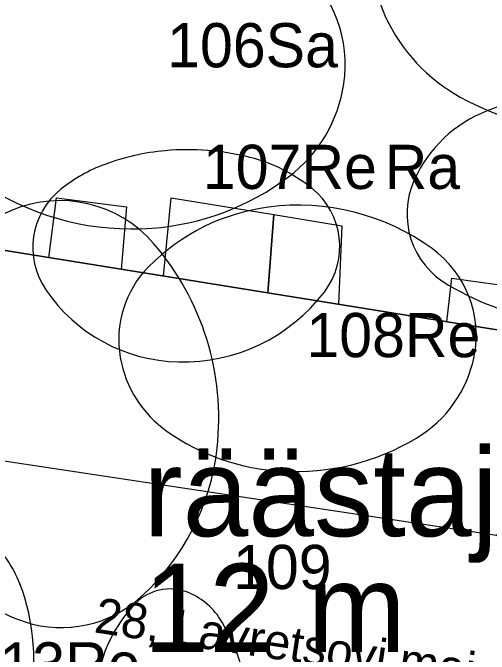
# Model space of a CAD drawing. Extents: x 738423 to 738903, y 6589762 to 6590172.
# Drawn here: x 738736.84 to 738753.01, y 6589853.54 to 6589875.33 of the extents above; entities that cross this region are included whole.
import ezdxf

# ---------------------------------------------------------------- set-up
doc = ezdxf.new("R2010")
doc.units = 0
for name, color, linetype in [('_1927_hoonestus', 7, 'Continuous'), ('_1927_katuse_kalded', 7, 'Continuous'), ('_a_olol_maapind', 7, 'Continuous'), ('_ajalooline_aadress', 7, 'Continuous'), ('a_dendro_II_Vkl_puu', 7, 'Continuous'), ('a_dendro_III_vk_puu', 7, 'Continuous'), ('a_dendro_puu_nr', 7, 'Continuous'), ('a_dendro_V_vk_puu', 7, 'Continuous'), ('Default', 7, 'Continuous')]:
    doc.layers.add(name, color=color, linetype=linetype)

# ---------------------------------------------------------------- blocks, each defined once
blk = doc.blocks.new('_U500')
at = {"layer": 'Default'}
for centre, radius, start, end in [((-0.003181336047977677, 0.010726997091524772), 0.005594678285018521, 70.00824536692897, 154.4975713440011), ((-0.004341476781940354, 0.007538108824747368), 0.008988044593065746, 25.436486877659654, 70.00824536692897), ((0.011580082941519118, 0.0036853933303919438), 0.021949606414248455, 154.49757134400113, 194.18050981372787), ((-0.018263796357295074, 0.0009164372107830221), 0.024404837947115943, 358.8256663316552, 25.436486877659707), ((-0.0137456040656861, 0.0008238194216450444), 0.019885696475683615, 335.045242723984, 358.8256663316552), ((0.0065598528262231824, 0.0024168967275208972), 0.01677159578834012, 194.18050981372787, 228.62130685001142), ((-0.0020266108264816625, -0.004629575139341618), 0.006959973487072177, 294.2825804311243, 335.045242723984), ((-0.0012209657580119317, -0.006415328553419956), 0.005000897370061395, 228.6213068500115, 294.2825804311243)]:
    blk.add_arc(centre, radius, start, end, dxfattribs=at)
blk = doc.blocks.new('_U502')
at = {"layer": 'Default'}
for centre, radius, start, end in [((0.0036572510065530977, 0.004633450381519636), 0.00959048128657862, 55.41358266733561, 119.34866517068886), ((0.004842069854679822, 0.0025263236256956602), 0.012007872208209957, 119.34866517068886, 155.37187783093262), ((-0.0003045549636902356, -0.0011124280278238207), 0.016569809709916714, 7.908336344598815, 55.413582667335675), ((0.010745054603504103, -0.00017977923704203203), 0.018501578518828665, 155.37187783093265, 184.22093899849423), ((-0.0007628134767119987, -0.0011760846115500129), 0.017032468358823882, 317.51230780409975, 7.908336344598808), ((0.010991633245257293, -0.00016158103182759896), 0.018748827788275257, 184.2209389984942, 213.03615061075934), ((0.005634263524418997, -0.0036455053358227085), 0.01235827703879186, 213.03615061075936, 248.72963133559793), ((0.004661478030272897, -0.006144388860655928), 0.009676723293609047, 248.72963133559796, 317.51230780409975)]:
    blk.add_arc(centre, radius, start, end, dxfattribs=at)
blk = doc.blocks.new('_U555')
at = {"layer": 'Default'}
for centre, radius, start, end in [((-0.004312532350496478, 0.003536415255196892), 0.0050895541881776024, 43.03836195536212, 128.56530609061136), ((-0.0004914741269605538, -0.0012560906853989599), 0.011218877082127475, 128.5653060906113, 182.99361229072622), ((-0.0083944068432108, -0.0002751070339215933), 0.010674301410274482, 24.572702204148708, 43.03836195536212), ((-0.013301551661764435, -0.0025189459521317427), 0.01607012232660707, 9.545113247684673, 24.57270220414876), ((-0.014308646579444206, -0.002688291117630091), 0.01709135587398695, 349.9959315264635, 9.545113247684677), ((0.0004151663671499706, -0.0012086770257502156), 0.012126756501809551, 182.99361229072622, 236.8517005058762), ((-0.008353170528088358, -0.003738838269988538), 0.011043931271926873, 325.61057428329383, 349.99593152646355), ((-0.0034354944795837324, -0.007104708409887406), 0.005084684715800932, 236.85170050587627, 325.61057428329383)]:
    blk.add_arc(centre, radius, start, end, dxfattribs=at)
blk = doc.blocks.new('_U556')
at = {"layer": 'Default'}
for centre, radius, start, end in [((0.0008585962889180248, 0.005017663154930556), 0.009782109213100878, 101.92949833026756, 152.32783538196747), ((0.0007009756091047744, 0.005763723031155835), 0.009019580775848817, 44.06830731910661, 101.92949833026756), ((-0.005511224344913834, -0.0002496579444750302), 0.017665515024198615, 3.6239622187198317, 44.06830731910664), ((0.008453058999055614, 0.0010351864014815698), 0.018357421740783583, 152.32783538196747, 188.54277977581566), ((-0.004957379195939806, -0.0002145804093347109), 0.017110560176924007, 323.29399507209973, 3.623962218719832), ((0.007725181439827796, 0.0009258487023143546), 0.017621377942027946, 188.54277977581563, 221.24473871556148), ((0.0016930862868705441, -0.005172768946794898), 0.00881524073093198, 265.8876585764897, 323.29399507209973), ((0.0017552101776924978, -0.0043087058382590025), 0.009681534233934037, 221.24473871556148, 265.8876585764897)]:
    blk.add_arc(centre, radius, start, end, dxfattribs=at)
blk = doc.blocks.new('_U557')
at = {"layer": 'Default'}
for centre, radius, start, end in [((0.0009168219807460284, 0.0031891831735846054), 0.007029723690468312, 49.6852980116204, 104.286675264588), ((0.001109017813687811, 0.0024344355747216), 0.007808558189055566, 104.286675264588, 149.17299111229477), ((-0.0036199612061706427, -0.0021576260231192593), 0.014041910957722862, 11.811793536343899, 49.68529801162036), ((0.0072482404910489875, -0.0012291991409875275), 0.014957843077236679, 149.17299111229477, 181.19652175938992), ((-0.005001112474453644, -0.0024464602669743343), 0.015452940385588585, 328.31163125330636, 11.811793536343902), ((0.008365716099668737, -0.0012058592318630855), 0.016075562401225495, 181.1965217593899, 215.2100419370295), ((0.0020888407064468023, -0.005635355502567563), 0.008393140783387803, 215.21004193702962, 262.96527315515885), ((0.0019526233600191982, -0.006739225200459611), 0.007280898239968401, 262.96527315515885, 328.31163125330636)]:
    blk.add_arc(centre, radius, start, end, dxfattribs=at)
blk = doc.blocks.new('_U560')
at = {"layer": 'Default'}
for centre, radius, start, end in [((0.00339859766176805, -0.012089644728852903), 0.019710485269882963, 70.12675947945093, 101.72724357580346), ((0.0030405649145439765, -0.010364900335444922), 0.01794897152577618, 101.72724357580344, 129.22704303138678), ((0.006378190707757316, -0.0038465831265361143), 0.01094543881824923, 27.263791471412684, 70.12675947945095), ((-0.00200913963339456, -0.004179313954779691), 0.009963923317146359, 129.22704303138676, 166.43322505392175), ((0.008627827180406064, -0.00268725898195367), 0.008414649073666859, 315.1631984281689, 27.263791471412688), ((-0.00387483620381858, -0.00372909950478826), 0.008044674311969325, 166.43322505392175, 226.4566374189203), ((0.001714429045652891, 0.004186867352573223), 0.01816394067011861, 267.93816240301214, 315.1631984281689), ((0.0016382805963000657, 0.0020717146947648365), 0.01604741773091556, 226.45663741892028, 267.93816240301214)]:
    blk.add_arc(centre, radius, start, end, dxfattribs=at)
blk = doc.blocks.new('_U561')
at = {"layer": 'Default'}
for centre, radius, start, end in [((-0.0032471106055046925, -0.010129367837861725), 0.014437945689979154, 78.49437099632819, 117.35483362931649), ((-0.0019616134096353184, -0.0038141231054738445), 0.007993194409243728, 50.23157484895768, 78.49437099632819), ((-0.008165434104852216, -0.0006226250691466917), 0.0037342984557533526, 117.35483362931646, 199.0584050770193), ((0.0013930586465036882, 0.00021679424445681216), 0.0027489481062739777, 1.026623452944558, 50.23157484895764), ((0.0011186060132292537, 0.00021187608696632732), 0.003023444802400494, 318.0268318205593, 1.0266234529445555), ((-0.007242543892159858, -0.00030379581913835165), 0.004710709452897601, 199.0584050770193, 259.8390365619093), ((-0.003091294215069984, 0.0039989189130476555), 0.008686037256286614, 293.05157128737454, 318.0268318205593), ((-0.0054696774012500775, 0.009588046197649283), 0.014760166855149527, 259.8390365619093, 293.0515712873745)]:
    blk.add_arc(centre, radius, start, end, dxfattribs=at)
blk = doc.blocks.new('_U563')
at = {"layer": 'Default'}
for centre, radius, start, end in [((-0.0011498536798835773, -0.006309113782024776), 0.012338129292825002, 87.06210191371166, 129.99611641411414), ((-0.001004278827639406, -0.003472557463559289), 0.009497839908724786, 49.93101198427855, 87.06210191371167), ((0.0030244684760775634, 0.0013169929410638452), 0.003239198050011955, 343.8549831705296, 49.93101198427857), ((-0.006769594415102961, 0.0003891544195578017), 0.003594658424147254, 129.99611641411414, 215.3727263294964), ((0.001656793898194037, 0.0017129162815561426), 0.004663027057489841, 307.1223988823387, 343.8549831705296), ((-0.004839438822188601, 0.001759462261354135), 0.005961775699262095, 215.3727263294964, 257.0506083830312), ((-0.0024608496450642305, 0.007152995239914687), 0.011485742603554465, 283.95889134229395, 307.1223988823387), ((-0.003052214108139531, 0.009532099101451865), 0.013937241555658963, 257.05060838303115, 283.95889134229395)]:
    blk.add_arc(centre, radius, start, end, dxfattribs=at)

msp = doc.modelspace()

# ---------------------------------------------------------------- linework, layer by layer
at = {"layer": '_1927_hoonestus'}
for points in [[(738754.6692785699, 6589871.594604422), (738760.36289178, 6589871.140155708), (738760.7214549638, 6589858.590853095), (738762.9217034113, 6589858.653719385), (738763.1765392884, 6589853.918763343), (738760.8559821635, 6589853.882554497), (738760.9939902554, 6589849.052428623), (738727.0653921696, 6589854.4155183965), (738729.4713935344, 6589879.48149063), (738730.9007906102, 6589879.344287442), (738730.7635874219, 6589877.914890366), (738731.4712535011, 6589877.903268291), (738731.3149034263, 6589876.439602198), (738734.6501282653, 6589876.083330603), (738734.035737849, 6589870.331734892), (738732.4870712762, 6589870.497164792), (738732.2152484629, 6589867.952504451), (738754.0513227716, 6589864.430896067)], [(738738.0638296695, 6589867.009275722), (738738.3227308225, 6589869.036637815), (738740.7006114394, 6589868.732974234), (738740.5195487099, 6589866.61323014)], [(738741.9506254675, 6589866.382433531), (738742.2126918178, 6589869.036637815), (738745.7038803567, 6589868.478495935), (738745.5012282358, 6589865.809810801)], [(738745.7038803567, 6589868.478495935), (738748.0090424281, 6589868.087088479), (738747.8978452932, 6589865.42329688), (738745.5012282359, 6589865.8098108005)], [(738751.5721327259, 6589864.83072693), (738751.7504285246, 6589866.314167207), (738754.1842644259, 6589865.972034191), (738754.0513227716, 6589864.430896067)]]:
    msp.add_lwpolyline(points, close=True, dxfattribs=at)
at = {"layer": '_1927_katuse_kalded'}
for points in [[(738753.2610349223, 6589857.584302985), (738760.578654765, 6589863.588697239), (738754.0513227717, 6589864.430896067), (738732.2152484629, 6589867.952504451), (738728.4114490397, 6589868.438878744), (738727.7392322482, 6589861.435654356)], [(738753.2610349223, 6589857.584302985), (738760.9939902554, 6589849.052428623), (738727.0653912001, 6589854.415518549), (738727.7392322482, 6589861.435654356)]]:
    msp.add_lwpolyline(points, close=True, dxfattribs=at)

# ---------------------------------------------------------------- block references
at = {"layer": 'a_dendro_II_Vkl_puu', "xscale": 500.0000000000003, "yscale": 500.0000000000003, "rotation": 85.69234851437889}
msp.add_blockref('_U502', (738756.0163105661, 6589875.209442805), dxfattribs=at)
at = {"layer": 'a_dendro_III_vk_puu', "xscale": 500.0000000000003, "yscale": 500.0000000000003, "rotation": 85.69234851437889}
for name, p in [('_U556', (738741.076, 6589872.910999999)), ('_U500', (738758.4873105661, 6589869.684442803)), ('_U560', (738736.7713153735, 6589860.5386774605))]:
    msp.add_blockref(name, p, dxfattribs=at)
at = {"layer": 'a_dendro_V_vk_puu', "xscale": 500.0000000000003, "yscale": 500.0000000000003, "rotation": 85.69234851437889}
for name, p in [('_U555', (738741.985, 6589869.367)), ('_U557', (738745.5009999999, 6589863.653)), ('_U561', (738735.156310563, 6589855.704442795)), ('_U563', (738742.7113105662, 6589852.580442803))]:
    msp.add_blockref(name, p, dxfattribs=at)

# ---------------------------------------------------------------- texts
at = {"layer": '_a_olol_maapind'}
for s, p in [('räästajoon ', (738741.2679981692, 6589857.548758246)), ('12 m', (738741.2679981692, 6589853.61228508))]:
    msp.add_text(s, height=3, dxfattribs=at).set_placement(p)
at = {"layer": '_ajalooline_aadress'}
msp.add_text('28, Lavretsovi maja', height=1.2, rotation=351.6029994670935, dxfattribs=at).set_placement((738739.5649350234, 6589854.2859480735))
at = {"layer": 'a_dendro_puu_nr'}
for s, p in [('106Sa', (738742.0767694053, 6589873.476628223)), ('107Re', (738743.2898280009, 6589869.344473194)), ('Ra', (738749.4647939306, 6589869.344473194)), ('108Re', (738746.8058280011, 6589863.630473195)), ('109', (738744.3159209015, 6589855.754651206)), ('113Re', (738735.2637145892, 6589852.444194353))]:
    msp.add_text(s, height=1.5, dxfattribs=at).set_placement(p)

doc.saveas('drawing.dxf')
